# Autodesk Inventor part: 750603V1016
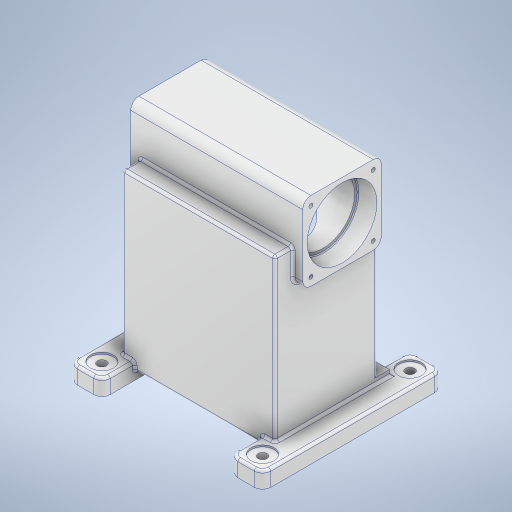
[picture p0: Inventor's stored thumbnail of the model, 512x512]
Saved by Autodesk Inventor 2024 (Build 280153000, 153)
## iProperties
Created: 2025-06
Part Number: 750603V1016
Material: 알루미늄 6061
Document SubType Name: Modeling
Designer: 11
Mass: 8009.62 g
Surface Area: 3457.08 cm^2
Volume: 2966.53 cm^3
Density: 2.7 g/cm^3
Appearance: 알루미늄 - 평지
Author: 11
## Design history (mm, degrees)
sketch "스케치1"
  geometry: L1 (-103, 70)-(103, 70); L2 (103, 70)-(103, -70); L3 (103, -70)-(-103, -70); L4 (-103, -70)-(-103, 70); L5 (103, -55)-(-86, -55); L6 (-86, -55)-(-86, -70); 4 further points
  constraints: 12 end point, 3 midpoint, 3 perpendicular, 2 parallel, 2 point on line, 1 horizontal, 1 horizontal alignment, 1 vertical alignment
  dimensions: "d0" = 206 distance of L2.end L3.end; "d1" = 140 distance of L1.end L2.end; "d8" = 15 distance between parallel lines of L3 L5; "d9" = 189 distance from line of point (-86, -62.5) L2
extrude "돌출1" new body sketch "스케치1" stored distance "d2" = 186; taper "d3" = 0 deg
sketch "스케치2"
  geometry: L1 (211, 180)-(-25, 180); L2 (-25, 180)-(-25, -40); L3 (-25, -40)-(211, -40); L4 (211, -40)-(211, 180); L5 (171, 180)-(171, -40); L6 (15, 180)-(15, -40); 3 further points
  constraints: 12 end point, 4 point on line, 3 perpendicular, 2 midpoint, 2 parallel, 1 horizontal, 1 horizontal alignment, 1 vertical alignment
  dimensions: "d4" = 236 distance of L2.end L3.end; "d10" = 220 distance of L3.end L1.start; "d11" = 40 distance between parallel lines of L2 L6; "d12" = 40 distance between parallel lines of L4 L5
extrude "돌출2" join sketch "스케치2" stored distance "d13" = 20; taper "d14" = 0 deg
sketch "스케치3"
  geometry: L1 (158, 38)-(158, -38); L2 (148, -48)-(72, -48); L3 (62, -38)-(62, 38); L4 (72, 48)-(148, 48); L5 (-113, -110)-(-113, 110) reference; L6 (-93, 70)-(103, 70) reference; L7 (103, 70)-(103, -55) reference; A1 r 10 centre (148, 38) between (158, 38) and (148, 48); A2 r 10 centre (148, -38) between (148, -48) and (158, -38); A3 r 10 centre (72, 38) between (72, 48) and (62, 38); A4 r 10 centre (72, -38) between (62, -38) and (72, -48); 8 further points
  constraints: 8 end point, 8 point on circle, 8 point on line, 8 tangent, 4 centre point, 3 midpoint, 3 perpendicular, 2 equal radius, 1 horizontal alignment, 1 vertical
  dimensions: "d15" = 271 distance between parallel lines of L5 L1; "d16" = 96 distance of point (158, 48) point (158, -48); "d17" = 96 distance of point (158, -48) point (62, -48); "d21" = 10 radius of A1 (derived); "d24" = 10 radius of A3 (derived)
extrude "돌출3" join sketch "스케치3" stored distance "d22" = 210; taper "d23" = 0 deg
node "작업 평면1"
sketch "스케치5"
  geometry: L1 (-12, 32)-(-12, 108) reference; L2 (198, 108)-(198, 32) reference; L3 (198, 22)-(198, 32) reference; L4 (198, 108)-(198, 118) reference; L5 (-12, 118)-(-12, 108) reference; L6 (-12, 32)-(-12, 22) reference; L7 (198, 70)-(-12, 70); L8 (-12, 70)-(-12, 27.5); L9 (11, 28.6)-(11, 31.5); L10 (11, 31.5)-(175, 31.5); L11 (175, 31.5)-(175, 28.6); L12 (186, 32)-(198, 32) reference; L13 (176.1, 27.5)-(198, 27.5); L14 (198, 70)-(198, 27.5); L15 (9.9, 27.5)-(-12, 27.5); L16 (-12, 32)-(0, 32) reference; A1 r 1.1 centre (9.9, 28.6) between (9.9, 27.5) and (11, 28.6); A2 r 1.1 centre (176.1, 28.6) between (175, 28.6) and (176.1, 27.5); 4 further points
  constraints: 16 end point, 5 midpoint, 4 perpendicular, 4 point on circle, 4 tangent, 2 centre point, 2 point on line, 1 equal radius, 1 parallel, 1 vertical
  dimensions: "d39" = 85 diameter of L15 L7; "d40" = 77 diameter of L10 L7; "d41" = 23 distance from line of L8 point (11, 30.05); "d42" = 23 horizontal distance of point (198, 27) point (175, 30.05); "d43" = 85 diameter of L13 L7; "d44" = 1.1 radius of A1 (derived)
revolve "회전2" sketch "스케치5" stored, may be unused: angle "d45" = 90 deg
sketch "스케치7"
  geometry: L1 (-86, -55)-(103, -55) reference; L2 (103, 70)-(-93, 70) reference; L3 (10, 70)-(10, -55); L4 (-113, 110)-(-113, -110) reference; L5 (10, -55)-(96, -55); L6 (96, -55)-(96, 47); L7 (96, 47)-(41, 47); L8 (41, 47)-(41, 62); L9 (40, 63)-(37, 63); L10 (37, 63)-(37, 63); L11 (34, 66)-(10, 66); A1 r 3 centre (34, 63) between (37, 63) and (34, 66); A2 r 1 centre (40, 62) between (41, 62) and (40, 63); 2 further points
  constraints: 16 end point, 6 perpendicular, 4 point on circle, 4 point on line, 4 tangent, 2 centre point, 1 vertical
  dimensions: "d68" = 123 distance between parallel lines of L4 L3; "d70" = 172 diameter of L6 L3; "d71" = 102 distance between parallel lines of L1 L7; "d72" = 16 distance between parallel lines of L7 L9; "d73" = 3 distance between parallel lines of L9 L11; "d74" = 62 diameter of L8 L3; "d75" = 54 diameter of L9.end L3; "d76" = 3 radius of A1 (derived); "d77" = 1 radius of A2
revolve "회전4" sketch "스케치7" stored, may be unused: angle "d78" = 90 deg
chamfer "모따기1" distance "d79" = 1; stored, may be unused: second distance "d80" = 2, angle "d81" = 45 deg
fillet "모깎기3" dims "d82" = 10
sketch "스케치8"
  geometry: L1 (171, -140)-(15, -140) reference; C1 r 14 at (191, -160); C2 r 5.5 at (191, -160); C3 r 14 at (-5, -160); C4 r 5.5 at (-5, -160); C5 r 14 at (191, 20); C6 r 5.5 at (191, 20); C7 r 14 at (-5, 20); C8 r 5.5 at (-5, 20); 2 further points
  constraints: 8 centre point, 6 equal radius, 4 coincident, 2 horizontal alignment, 2 vertical alignment, 1 midpoint
  dimensions: "d83" = 11 diameter of C2; "d84" = 28 diameter of C1; "d85" = 98 horizontal distance of point (93, -140) C1.centre; "d86" = 90 vertical distance of point (93, -70) C1.centre; "d87" = 90 vertical distance of point (93, -70) C5.centre; "d88" = 98 horizontal distance of point (93, -140) C3.centre
extrude "돌출4" cut sketch "스케치8" extent not by distance; stored distance "d89" = 0; taper "d90" = 0 deg
extrude "돌출5" cut sketch "스케치8" distance "d91" = 2; taper "d92" = 0 deg
fillet "모깎기4" dims "d93" = 3
sketch "스케치9"
  geometry: C1 r 42.5 at (0, 110) reference; 5 further points
  constraints: 2 horizontal alignment, 2 vertical alignment
  dimensions: "d101" = 38 horizontal distance of C1.centre point (-38, 147.096); "d102" = 38 horizontal distance of C1.centre point (-38, 72); "d103" = 38 horizontal distance of point (38, 147.096) C1.centre
hole "구멍1" sketch "스케치9" at (-38, 147.096), (38, 147.096), (38, 72), (-38, 72) diameter "d94" = 4.917; stored, may be unused: countersink angle "d98" = 90 deg, drill point angle "d100" = 118 deg; dims "d95" = 12, "d96" = 4, "d97" = 2, "d99" = 14
sketch "스케치10"
  geometry: L1 (183, 0)-(0, 0) reference; L2 (0, -189)-(0, 0) reference; L3 (186, -189)-(0, -189) reference; L4 (186, -3)-(186, -189) reference; C1 r 87 at (93, -93) reference; A1 r 3 centre (183, -3) between (186, -3) and (183, 0) reference; 5 further points
  constraints: 2 horizontal alignment, 1 vertical alignment
  dimensions: "d113" = 75 horizontal distance of C1.centre point (18, -18); "d114" = 75 horizontal distance of C1.centre point (18, -18); "d115" = 75 horizontal distance of point (18, -168) C1.centre; "d116" = 75 horizontal distance of C1.centre point (18, -168); "d117" = 75 horizontal distance of point (168, -168) C1.centre
  node "투영된 루프1"
hole "구멍2" sketch "스케치10" diameter "d104" = 6.647; stored, may be unused: countersink angle "d108" = 90 deg, drill point angle "d110" = 118 deg; dims "d105" = 16, "d106" = 4, "d107" = 2, "d109" = 18
hole "구멍3" sketch "스케치10" diameter "d118" = 6.647; stored, may be unused: countersink angle "d122" = 90 deg, drill point angle "d124" = 118 deg; dims "d119" = 16, "d120" = 4, "d121" = 2, "d123" = 18
sketch "스케치11"
  geometry: L1 (0, 10)-(210, 10) reference; 2 further points
  constraints: 1 vertical alignment, 1 other
  dimensions: "d125" = 30 distance from line of L1 point (105, -20)
feature "엠보싱1" sketch "스케치11" dims "d0" = 206, "d1" = 140, "d8" = 15, "d9" = 189, "d126" = 0.5, "d127" = 0
fillet "모깎기5" dims "d128" = 3
node "솔리드1"
mirror "미러1"
feature "A9D066F2-1C7D-4E18-AEED-F7BC21143FA4" dims "d104" = 6.647, "d105" = 16, "d106" = 4, "d107" = 2, "d108" = 90 deg, "d109" = 18, "d110" = 118 deg
other parameters: "d38" = -223
